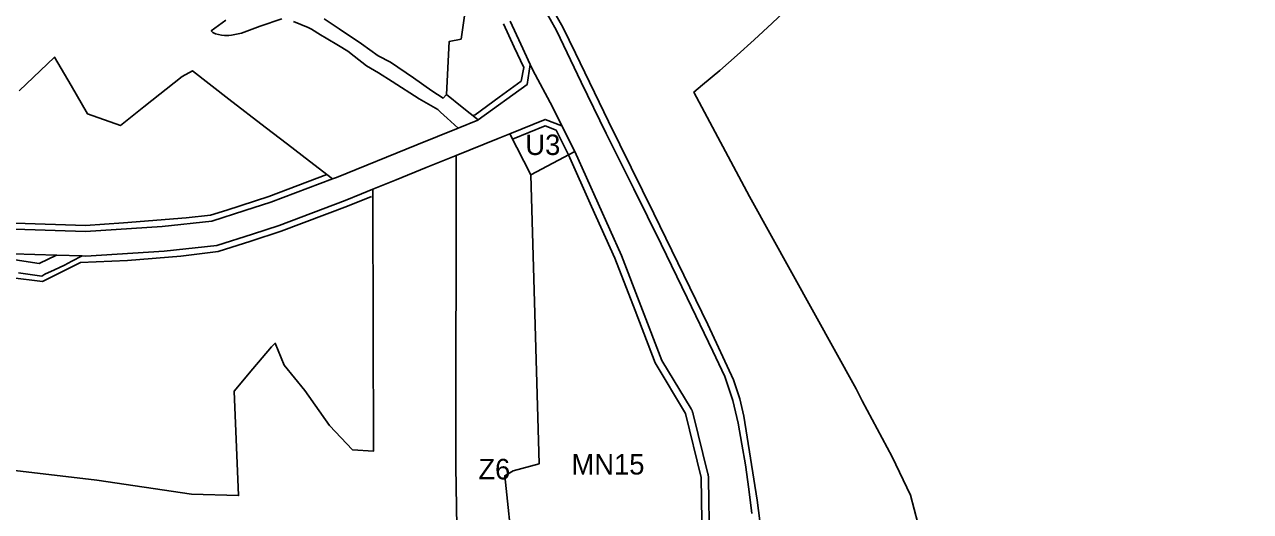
# Model space of a CAD drawing. Extents: x 7439486 to 7443435, y 5551288 to 5554556.
# Drawn here: x 7440457 to 7441056, y 5552234 to 5552472 of the extents above; entities that cross this region are included whole.
import ezdxf

# ---------------------------------------------------------------- set-up
doc = ezdxf.new("R2010")
doc.units = 0
for name, color, linetype in [('linie_rozgraniczajace', 7, 'Continuous'), ('linie_zabudowy_nieprzekraczalne', 7, 'Continuous'), ('oznaczenia_przeznaczen', 7, 'Continuous')]:
    doc.layers.add(name, color=color, linetype=linetype)

msp = doc.modelspace()

# ---------------------------------------------------------------- linework, layer by layer
at = {"layer": 'linie_rozgraniczajace'}
for points in [[(7440784.09, 5552438.75), (7440788.29, 5552442.28), (7440796.71, 5552449.34), (7440805.16, 5552456.78), (7440813.62, 5552464.22), (7440822.38, 5552472.46), (7440831.14, 5552480.7), (7440841.01, 5552490.47), (7440850.87, 5552500.24), (7440860.32, 5552509.94), (7440861.3, 5552510.94), (7440872.68, 5552522.16), (7440937.87, 5552579.63), (7441018.76, 5552711.22), (7441030.31, 5552730.01), (7441199.76, 5553005.69)], [(7441199.76, 5553005.69), (7441030.31, 5552730.01), (7441018.76, 5552711.22), (7440937.87, 5552579.63), (7440872.68, 5552522.16), (7440861.3, 5552510.94), (7440860.32, 5552509.94), (7440850.87, 5552500.24), (7440841.01, 5552490.47), (7440831.14, 5552480.7), (7440822.38, 5552472.46), (7440813.62, 5552464.22), (7440805.16, 5552456.78), (7440796.71, 5552449.34), (7440788.29, 5552442.28), (7440784.09, 5552438.75), (7440811.19, 5552387.81), (7440863.47, 5552293.77), (7440866.42, 5552287.9), (7440881.12, 5552260.61), (7440890.03, 5552241.86), (7440895.39, 5552221.28), (7440904.26, 5552212.34)], [(7440674.99, 5552497.99), (7440670.23, 5552464.67), (7440664.29, 5552463.45), (7440663.13, 5552437.52), (7440661.48, 5552435.85), (7440655.94, 5552439.42), (7440646.94, 5552445.7), (7440635.7, 5552453.3), (7440629.62, 5552456.51), (7440621.44, 5552462.3), (7440610.5, 5552469.61), (7440603.26, 5552474.45)], [(7440694.17, 5552473.42), (7440699.41, 5552462.15), (7440704.02, 5552452.16), (7440702.45, 5552442.45), (7440678.58, 5552425.14), (7440670.76, 5552431.41), (7440663.13, 5552437.52), (7440664.29, 5552463.45), (7440670.23, 5552464.67), (7440674.99, 5552497.99)], [(7440812.35, 5552232.97), (7440810.86, 5552244.81), (7440809.37, 5552256.65), (7440807.54, 5552266.86), (7440805.7, 5552277.08), (7440804.44, 5552282.56), (7440803.19, 5552288.05), (7440801.19, 5552293.97), (7440799.19, 5552299.9), (7440796.24, 5552306.03), (7440793.29, 5552312.17), (7440780.71, 5552338.32), (7440768.13, 5552364.47), (7440754.63, 5552391.46), (7440741.12, 5552418.46), (7440729.01, 5552443.64), (7440716.91, 5552468.82), (7440713.78, 5552474.29), (7440710.66, 5552479.76), (7440707.54, 5552485.24), (7440707.27, 5552486.63)], [(7440555.1, 5552473.84), (7440548.03, 5552468.66), (7440548.76, 5552467.92), (7440550.1, 5552467.2), (7440553.09, 5552466.51), (7440554.55, 5552466.34), (7440556.67, 5552466.33), (7440557.89, 5552466.5), (7440559.53, 5552466.84), (7440562.8, 5552467.49), (7440571.93, 5552470.9), (7440582.46, 5552474.6)], [(7440582.46, 5552474.6), (7440571.93, 5552470.9), (7440562.8, 5552467.49), (7440559.53, 5552466.84), (7440557.89, 5552466.5), (7440556.67, 5552466.33), (7440554.55, 5552466.34), (7440553.09, 5552466.51), (7440550.1, 5552467.2), (7440548.76, 5552467.92), (7440548.03, 5552468.66), (7440555.1, 5552473.84)], [(7440603.26, 5552474.45), (7440610.5, 5552469.61), (7440621.44, 5552462.3), (7440629.62, 5552456.51), (7440635.7, 5552453.3), (7440646.94, 5552445.7), (7440655.94, 5552439.42), (7440661.48, 5552435.85), (7440663.13, 5552437.52), (7440670.76, 5552431.41), (7440678.58, 5552425.14), (7440678.47, 5552425.06), (7440668.76, 5552421.14), (7440663.42, 5552425.93), (7440660.18, 5552429.01), (7440658.89, 5552430.24), (7440649.76, 5552435.5), (7440636.53, 5552443.91), (7440629.77, 5552448.2), (7440623.95, 5552451.57), (7440617.91, 5552456.35), (7440614.79, 5552458.67), (7440610.28, 5552461.44), (7440604.25, 5552465.14), (7440601.47, 5552466.79), (7440597.09, 5552469.54), (7440595.48, 5552470.23), (7440588.16, 5552473.21)], [(7440791.68, 5552218.68), (7440791.26, 5552249.64), (7440791.25, 5552249.86), (7440791.24, 5552250.08), (7440791.23, 5552250.3), (7440791.21, 5552250.51), (7440791.19, 5552250.73), (7440791.17, 5552250.95), (7440791.14, 5552251.17), (7440791.1, 5552251.38), (7440791.07, 5552251.6), (7440791.03, 5552251.81), (7440790.98, 5552252.03), (7440790.93, 5552252.24), (7440790.91, 5552252.35), (7440783.7, 5552281.51), (7440783.64, 5552281.72), (7440783.58, 5552281.94), (7440783.52, 5552282.15), (7440783.46, 5552282.35), (7440783.39, 5552282.56), (7440783.31, 5552282.77), (7440783.23, 5552282.97), (7440783.15, 5552283.18), (7440783.07, 5552283.38), (7440782.98, 5552283.58), (7440782.89, 5552283.78), (7440782.79, 5552283.97), (7440782.78, 5552283.99), (7440768.33, 5552307.68), (7440748.68, 5552358.99), (7440725.83, 5552409.66), (7440719.54, 5552422.26), (7440714.87, 5552431.61), (7440705.24, 5552449.5), (7440704.02, 5552452.16), (7440699.41, 5552462.15), (7440694.17, 5552473.42)], [(7440713.78, 5552474.29), (7440716.91, 5552468.82), (7440729.01, 5552443.64), (7440741.12, 5552418.46), (7440754.63, 5552391.46), (7440768.13, 5552364.47), (7440780.71, 5552338.32), (7440793.29, 5552312.17), (7440796.24, 5552306.03), (7440799.19, 5552299.9), (7440801.19, 5552293.97), (7440803.19, 5552288.05), (7440804.44, 5552282.56), (7440805.7, 5552277.08), (7440807.54, 5552266.86), (7440809.37, 5552256.65), (7440810.86, 5552244.81), (7440812.35, 5552232.97)], [(7440588.16, 5552473.21), (7440595.48, 5552470.23), (7440597.09, 5552469.54), (7440601.47, 5552466.79), (7440604.25, 5552465.14), (7440610.28, 5552461.44), (7440614.79, 5552458.67), (7440617.91, 5552456.35), (7440623.95, 5552451.57), (7440629.77, 5552448.2), (7440636.53, 5552443.91), (7440649.76, 5552435.5), (7440658.89, 5552430.24), (7440660.18, 5552429.01), (7440663.42, 5552425.93), (7440668.76, 5552421.14), (7440648.63, 5552412.99), (7440609.21, 5552397.04), (7440607.25, 5552396.3), (7440596.05, 5552404.94), (7440585.24, 5552413.27), (7440574.44, 5552421.6), (7440556.62, 5552435.33), (7440538.81, 5552449.07), (7440533.74, 5552446.35), (7440515.03, 5552431.52), (7440503.61, 5552422.47), (7440487.47, 5552428.19), (7440479.43, 5552441.91), (7440471.3, 5552455.81), (7440453.98, 5552439.3)], [(7440453.98, 5552439.3), (7440471.3, 5552455.81), (7440479.43, 5552441.91), (7440487.47, 5552428.19), (7440503.61, 5552422.47), (7440515.03, 5552431.52), (7440533.74, 5552446.35), (7440538.81, 5552449.07), (7440556.62, 5552435.33), (7440574.44, 5552421.6), (7440585.24, 5552413.27), (7440596.05, 5552404.94), (7440607.25, 5552396.3), (7440577.22, 5552384.99), (7440564.42, 5552380.85), (7440548.24, 5552375.62), (7440524.01, 5552373.04), (7440486.55, 5552370.64), (7440451.96, 5552371.77)], [(7440451.96, 5552371.77), (7440486.55, 5552370.64), (7440524.01, 5552373.04), (7440548.24, 5552375.62), (7440564.42, 5552380.85), (7440577.22, 5552384.99), (7440607.25, 5552396.3), (7440609.21, 5552397.04), (7440648.63, 5552412.99), (7440668.76, 5552421.14), (7440678.47, 5552425.06), (7440678.58, 5552425.14), (7440702.45, 5552442.45), (7440704.02, 5552452.16), (7440705.24, 5552449.5), (7440714.87, 5552431.61), (7440719.54, 5552422.26), (7440711.37, 5552425.43), (7440694.01, 5552418.41), (7440688.29, 5552416.09), (7440667.72, 5552407.77), (7440653.13, 5552401.87), (7440638.41, 5552395.91), (7440626.99, 5552391.29), (7440621.5, 5552389.07), (7440613.58, 5552385.86), (7440581.18, 5552373.66), (7440568.12, 5552369.43), (7440550.75, 5552363.82), (7440525.03, 5552361.08), (7440486.74, 5552358.63), (7440484.82, 5552358.69), (7440472.39, 5552359.1), (7440451.15, 5552359.79)], [(7440895.39, 5552221.28), (7440890.03, 5552241.86), (7440881.12, 5552260.61), (7440866.42, 5552287.9), (7440863.47, 5552293.77), (7440811.19, 5552387.81), (7440784.09, 5552438.75)], [(7440670.36, 5552089.49), (7440667.55, 5552255.86), (7440667.72, 5552407.77), (7440688.29, 5552416.09), (7440694.01, 5552418.41), (7440704.29, 5552398.34), (7440708.38, 5552257.24), (7440695.68, 5552253.78), (7440691.52, 5552251.37), (7440693.2, 5552235.79), (7440694.88, 5552220.22)], [(7440426.81, 5552256.92), (7440492.04, 5552249.24), (7440515.18, 5552245.79), (7440538.31, 5552242.34), (7440561.36, 5552241.65), (7440559.29, 5552292.73), (7440568.35, 5552303.55), (7440577.41, 5552314.36), (7440579.29, 5552316.07), (7440583.73, 5552305.35), (7440588.78, 5552299.18), (7440593.84, 5552293.01), (7440605.85, 5552275.97), (7440617.12, 5552263.96), (7440627.29, 5552263.31), (7440627.08, 5552385.22), (7440626.99, 5552391.29), (7440638.41, 5552395.91), (7440653.13, 5552401.87), (7440667.72, 5552407.77), (7440667.55, 5552255.86), (7440670.36, 5552089.49)], [(7440694.88, 5552220.22), (7440693.2, 5552235.79), (7440691.52, 5552251.37), (7440695.68, 5552253.78), (7440708.38, 5552257.24), (7440704.29, 5552398.34), (7440715.06, 5552404), (7440725.83, 5552409.66), (7440748.68, 5552358.99), (7440768.33, 5552307.68), (7440782.78, 5552283.99), (7440782.79, 5552283.97), (7440782.89, 5552283.78), (7440782.98, 5552283.58), (7440783.07, 5552283.38), (7440783.15, 5552283.18), (7440783.23, 5552282.97), (7440783.31, 5552282.77), (7440783.39, 5552282.56), (7440783.46, 5552282.35), (7440783.52, 5552282.15), (7440783.58, 5552281.94), (7440783.64, 5552281.72), (7440783.7, 5552281.51), (7440790.91, 5552252.35), (7440790.93, 5552252.24), (7440790.98, 5552252.03), (7440791.03, 5552251.81), (7440791.07, 5552251.6), (7440791.1, 5552251.38), (7440791.14, 5552251.17), (7440791.17, 5552250.95), (7440791.19, 5552250.73), (7440791.21, 5552250.51), (7440791.23, 5552250.3), (7440791.24, 5552250.08), (7440791.25, 5552249.86), (7440791.26, 5552249.64), (7440791.68, 5552218.68)], [(7440453.78, 5552350.49), (7440465.1, 5552348.83), (7440466.59, 5552349.77), (7440471.39, 5552352.01), (7440476.2, 5552354.26), (7440479.81, 5552356.12), (7440484.82, 5552358.69), (7440486.74, 5552358.63), (7440525.03, 5552361.08), (7440550.75, 5552363.82), (7440568.12, 5552369.43), (7440581.18, 5552373.66), (7440613.58, 5552385.86), (7440621.5, 5552389.07), (7440626.99, 5552391.29), (7440627.08, 5552385.22), (7440627.29, 5552263.31), (7440617.12, 5552263.96), (7440605.85, 5552275.97), (7440593.84, 5552293.01), (7440588.78, 5552299.18), (7440583.73, 5552305.35), (7440579.29, 5552316.07), (7440577.41, 5552314.36), (7440568.35, 5552303.55), (7440559.29, 5552292.73), (7440561.36, 5552241.65), (7440538.31, 5552242.34), (7440515.18, 5552245.79), (7440492.04, 5552249.24), (7440426.81, 5552256.92)], [(7440451.15, 5552359.79), (7440472.39, 5552359.1), (7440463.8, 5552355.09), (7440443.41, 5552358.06)], [(7440443.41, 5552358.06), (7440463.8, 5552355.09), (7440472.39, 5552359.1), (7440484.82, 5552358.69), (7440479.81, 5552356.12), (7440476.2, 5552354.26), (7440471.39, 5552352.01), (7440466.59, 5552349.77), (7440465.1, 5552348.83), (7440453.78, 5552350.49)]]:
    msp.add_lwpolyline(points, dxfattribs=at)
msp.add_lwpolyline([(7440694.01, 5552418.41), (7440711.37, 5552425.43), (7440719.54, 5552422.26), (7440725.83, 5552409.66), (7440715.06, 5552404), (7440704.29, 5552398.34)], close=True, dxfattribs=at)
at = {"layer": 'linie_zabudowy_nieprzekraczalne'}
for points in [[(7440820.32, 5552197.72), (7440815.07, 5552239.39), (7440811.79, 5552259.94), (7440808.51, 5552280.49), (7440806.56, 5552289), (7440803.45, 5552298.21), (7440790.9, 5552325.21), (7440764.52, 5552379.51), (7440742.31, 5552424.31), (7440726.11, 5552457.74), (7440720.01, 5552470.44), (7440715.43, 5552478.46), (7440710.86, 5552486.47), (7440710.78, 5552486.89), (7440710.86, 5552488.83), (7440715.68, 5552492.36), (7440722.02, 5552497.81), (7440737.23, 5552509.98), (7440774.12, 5552538.84), (7440794.17, 5552566.49), (7440831.37, 5552619.67), (7440910.95, 5552737.79), (7440979.56, 5552840.3), (7441030.3, 5552920.28)], [(7440675.92, 5552427.27), (7440677.01, 5552427.71), (7440688.85, 5552436.29), (7440699.65, 5552444.13), (7440700.84, 5552450.69), (7440696.24, 5552460.68), (7440690.93, 5552472.1)], [(7440791.88, 5552167.52), (7440787.03, 5552205.99), (7440788.18, 5552218.81), (7440787.69, 5552250.56), (7440779.98, 5552281.69), (7440765.06, 5552306.43), (7440755.26, 5552332.04), (7440745.45, 5552357.65), (7440734.06, 5552382.9), (7440722.7, 5552408.1), (7440716.68, 5552420.15), (7440711.39, 5552422.2), (7440695.35, 5552415.8)], [(7440452.16, 5552374.77), (7440486.5, 5552373.64), (7440505.13, 5552374.84), (7440535.69, 5552377.3), (7440547.61, 5552378.57), (7440555.56, 5552381.13), (7440576.23, 5552387.82), (7440604.46, 5552398.46)], [(7440626.34, 5552387.79), (7440614.67, 5552383.07), (7440582.17, 5552370.83), (7440567.34, 5552365.94), (7440551.39, 5552360.83), (7440533.17, 5552358.59), (7440507.08, 5552356.55), (7440484.03, 5552355.43), (7440465.41, 5552346.3), (7440449.58, 5552348.23)]]:
    msp.add_lwpolyline(points, dxfattribs=at)

# ---------------------------------------------------------------- texts
at = {"layer": 'oznaczenia_przeznaczen'}
for s, p in [('U3', (7440701.63, 5552408.02)), ('Z6', (7440678.64, 5552249.59)), ('MN15', (7440724.21, 5552251.95))]:
    msp.add_text(s, height=10, dxfattribs=at).set_placement(p)

doc.saveas('drawing.dxf')
